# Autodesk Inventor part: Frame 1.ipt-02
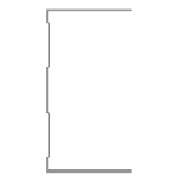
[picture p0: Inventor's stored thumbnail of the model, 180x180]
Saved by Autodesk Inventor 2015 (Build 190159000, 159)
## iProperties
Created: 2015-04
Part Number: Frame 1.ipt-02
Material: Aluminum 6061
Description: Kévin Novo
Document SubType Name: Modeling
Standard: Kevin
Designer: suporte
Standards Organization: Kevin
Language: en-US
Size Designation: (Unnamed 2)
Categories: <MemberInstance><Categories><Category DisplayName="Structural Shapes" InternalName="089c4875-fa83-4c05-b084-43b9cc11f5ed" Mnemonic="GRDR"><CategoryParameter Dis
Density: 2.7 g/cm^3
Appearance: Aluminum - Flat
IsCustomPart: 1
G_W: 50,000 mm
G_H: 75,000 mm
G_L: 470,645 mm
+C6D07C4E-F784-4905-9E85-D001DAC4732C+CUTDETAIL2: Miter 67,49 deg
+9BC56BD3-3601-4756-9CD3-DFE412EE9504+CUTDETAIL3: Miter 67,51 deg
_CCFamilyMember: 2
_CCFamilyDisplayName: Kévin - Kévin Novo
_FrameMemberDoc: Frame Member File
_Version: 15.0.0
_GetPNFromCC: 1
Author: suporte
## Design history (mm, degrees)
node "Start Plane"
node "End Plane"
sketch "Sketch"
  geometry: L1 (24.7, 37.5)-(24.7, 36.9); L2 (24.7, 36.9)-(-24.7, 36.9); L3 (-24.7, -36.9)-(24.7, -36.9); L4 (24.7, -36.9)-(24.7, -37.5); L5 (24.7, -37.5)-(-25.3, -37.5); L6 (-25.3, 37.5)-(24.7, 37.5); L7 (-24.7, 36.9)-(-24.7, 31.9); L8 (-24.7, 31.9)-(-23.3, 30.5); L9 (-23.3, 30.5)-(-23.3, 10.934); L10 (-23.3, 10.934)-(-24.7, 9.534); L11 (-24.7, 9.534)-(-24.7, -9.534); L12 (-24.7, -9.534)-(-23.3, -10.934); L13 (-23.3, -10.934)-(-23.3, -30.5); L14 (-23.3, -30.5)-(-24.7, -31.9); L15 (-24.7, -31.9)-(-24.7, -36.9); L16 (-25.3, -37.5)-(-25.3, -31.651); L17 (-25.3, -31.651)-(-23.9, -30.251); L18 (-23.9, -30.251)-(-23.9, -11.183); L19 (-23.9, -11.183)-(-25.3, -9.783); L20 (-25.3, -9.783)-(-25.3, 9.783); L21 (-25.3, 9.783)-(-23.9, 11.183); L22 (-23.9, 11.183)-(-23.9, 30.251); L23 (-23.9, 30.251)-(-25.3, 31.651); L24 (-25.3, 31.651)-(-25.3, 37.5); L25 (-25.3, 0)-(30.37, 0); 3 further points
  constraints: 50 end point, 10 point on line, 9 parallel, 5 perpendicular, 4 equal length, 3 midpoint, 3 vertical, 2 vertical alignment, 1 collinear, 1 horizontal, 1 horizontal alignment
  dimensions: "d3" = 0.6 distance of L1.start L1.end (= d6); "d5" = 75 distance between parallel lines of L5 L6; "d6" = 0.6 distance between parallel lines of L24 L7 (= d8); "d7" = 0.6 distance between parallel lines of L8 L23 (= d8); "d8" = 0.6 distance between parallel lines of L22 L9 (= d12); "Espessura" = 0.6 distance between parallel lines of L17 L14; "d10" = 0.6 distance between parallel lines of L13 L18 (= Espessura); "d11" = 0.6 distance between parallel lines of L12 L19 (= Espessura); "d12" = 0.6 distance between parallel lines of L21 L10 (= d11); "d13" = 5 distance of L2.end L7.end; "d15" = 135 deg angle of L9 L8; "d16" = 2 distance between parallel lines of L24 L9; "d17" = 50 distance of L6.start L1.start
extrude "Body" join sketch "Sketch" stored distance "d24" = 0.13; taper "d25" = 0 deg
node "Driven Length"
  sketch "Sketch10"
    geometry: L1 (0, 0)-(10, 0) reference
    constraints: 2 end point, 1 horizontal
  workplane "Work Plane7"
  sketch "Sketch11"
    geometry: L1 (-2, -36.226)-(12, -36.226) reference; L2 (-2, 434.419)-(12, 434.419) reference
    dimensions: "d27" = 470.64466 distance between parallel lines of L1 L2 (derived)
workplane "Work Plane9"
split "Split2"
workplane "Work Plane10"
split "Split3"
body "Solid1"
other parameters: "tamanho" = 398.15728, "G_OFFSET_START" = 36.22585 [user parameter; used in 1 equation term], "G_OFFSET_END" = 36.26152 [user parameter; used in 1 equation term], "d22" = -36.22585 (= -G_OFFSET_START), "d23" = 434.41881 (= tamanho + G_OFFSET_END), "G_L" = 470.64466 (= d27) [user parameter], "d34" = 90 deg
